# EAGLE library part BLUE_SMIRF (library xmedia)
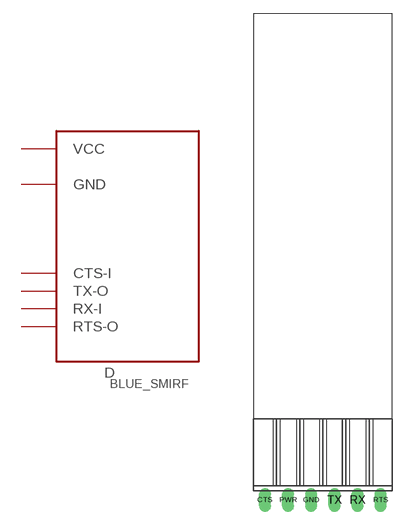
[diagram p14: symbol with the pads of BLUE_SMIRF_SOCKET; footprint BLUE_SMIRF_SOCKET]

Designator prefix D

## BLUE_SMIRF  [BLUE_SMIRF_SOCKET]
CTS  CTS-I  in
GND  GND  sup
PWR  VCC  sup
RTS  RTS-O  out
RX  RX-I  in
TX  TX-O  out

## Footprint BLUE_SMIRF_SOCKET (pad centres in mm)
drill 0.813 long: CTS -6.35,-8.89; GND -1.27,-8.89; PWR -3.81,-8.89; RTS 6.35,-8.89; RX 3.81,-8.89; TX 1.27,-8.89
